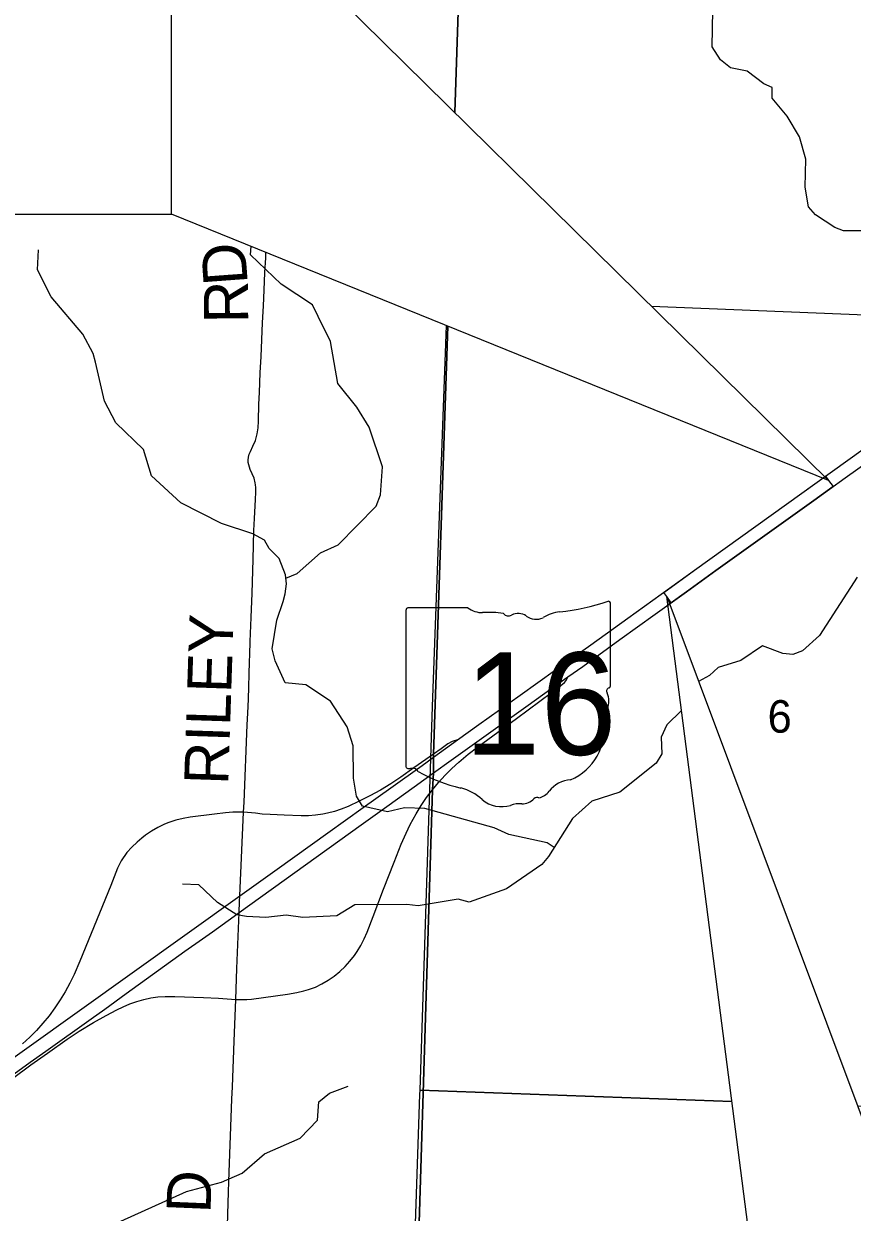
# Model space of a CAD drawing. Extents: x 0 to 34, y 0 to 22.
# Drawn here: x 25.673 to 26.74, y 15.788 to 17.319 of the extents above; entities that cross this region are included whole.
import ezdxf

# ---------------------------------------------------------------- set-up
doc = ezdxf.new("R2010")
doc.units = 0
for name, color, linetype in [('GM_X_Interchange_Ramps', 7, 'Continuous'), ('GM_X_Minor_River', 7, 'Continuous'), ('GM_X_Section', 7, 'Continuous'), ('GM_X_Section_Text', 7, 'Continuous'), ('GM_X_State_Location', 7, 'Continuous'), ('GM_X_State_Route', 7, 'Continuous'), ('GM_X_State_Shield', 7, 'Continuous'), ('GM_X_Township', 7, 'Continuous'), ('GM_X_Township_Road', 7, 'Continuous'), ('GM_X_Township_Road_Text', 7, 'Continuous'), ('SH_Data', 7, 'Continuous'), ('SH_Text', 7, 'Continuous')]:
    doc.layers.add(name, color=color, linetype=linetype)

msp = doc.modelspace()

# ---------------------------------------------------------------- linework, layer by layer
at = {"layer": 'GM_X_Interchange_Ramps'}
for points in [[(25.9458, 16.0619), (25.96, 16.0619), (25.9661, 16.0624), (26.0124, 16.0688), (26.0246, 16.0709), (26.0337, 16.073), (26.0397, 16.0748), (26.0485, 16.0781), (26.0569, 16.0821), (26.065, 16.0868), (26.0727, 16.0921), (26.0799, 16.098), (26.0867, 16.1044), (26.093, 16.1113), (26.0987, 16.1187), (26.1023, 16.1238), (26.1071, 16.1318), (26.1113, 16.1401), (26.1152, 16.1486), (26.123, 16.169), (26.1362, 16.204), (26.1497, 16.2388), (26.159, 16.262), (26.1653, 16.2762), (26.1707, 16.2874), (26.1782, 16.3011), (26.1847, 16.3117), (26.1917, 16.322), (26.1991, 16.332), (26.2071, 16.3416), (26.2154, 16.3508), (26.2242, 16.3596), (26.2334, 16.3679), (26.2454, 16.3779), (26.2577, 16.3874), (26.3073, 16.424), (26.3526, 16.4574), (26.3597, 16.4625), (26.3692, 16.4704), (26.3714, 16.473), (26.3738, 16.4775)], [(26.2315, 16.3964), (26.2246, 16.3943), (26.2191, 16.3913), (26.2103, 16.3849), (26.2007, 16.3781), (26.1753, 16.3603), (26.1584, 16.3484), (26.1454, 16.3398), (26.1321, 16.3318), (26.1185, 16.3243), (26.1046, 16.3173), (26.0905, 16.3108), (26.0818, 16.3073), (26.073, 16.3043), (26.064, 16.3019), (26.0579, 16.3007), (26.0487, 16.2994), (26.0394, 16.2988), (26.0301, 16.2987), (26.0084, 16.2996), (25.9903, 16.3003), (25.9798, 16.3009), (25.9714, 16.3019), (25.956, 16.3034)], [(25.956, 16.3034), (25.9467, 16.3035), (25.9422, 16.3034), (25.9327, 16.3026), (25.9183, 16.3009), (25.8873, 16.2967), (25.878, 16.2951), (25.8688, 16.293), (25.8598, 16.2902), (25.854, 16.2879), (25.8455, 16.2837), (25.8373, 16.279), (25.8296, 16.2736), (25.8248, 16.2697), (25.8189, 16.2647), (25.812, 16.2581), (25.8057, 16.2512), (25.7983, 16.2405), (25.7936, 16.2314), (25.7848, 16.2089), (25.745, 16.1112), (25.7375, 16.0941), (25.732, 16.083), (25.726, 16.0721), (25.7196, 16.0615), (25.7127, 16.0512), (25.7053, 16.0412), (25.6974, 16.0316), (25.6891, 16.0223), (25.6804, 16.0135), (25.6713, 16.0051)], [(25.6147, 15.9334), (25.6254, 15.9375), (25.6324, 15.9416), (25.6817, 15.978), (25.7032, 15.993), (25.7285, 16.0109), (25.7441, 16.0211), (25.7627, 16.0324), (25.7788, 16.0416), (25.7926, 16.0488), (25.801, 16.0528), (25.8096, 16.0565), (25.8183, 16.0596), (25.8273, 16.0621), (25.8364, 16.064), (25.8456, 16.0654), (25.8548, 16.066), (25.8673, 16.066), (25.9044, 16.0644), (25.9234, 16.0637), (25.9458, 16.0619)]]:
    msp.add_lwpolyline(points, dxfattribs=at)
at = {"layer": 'GM_X_Minor_River'}
for points in [[(26.753, 17.052), (26.7288, 17.0519), (26.7174, 17.0564), (26.6927, 17.0726), (26.6836, 17.0828), (26.6793, 17.1082), (26.6803, 17.1443), (26.6719, 17.1731), (26.6562, 17.1996), (26.6368, 17.2231), (26.6368, 17.2367), (26.6261, 17.2412), (26.6045, 17.2575), (26.5833, 17.2619), (26.5704, 17.2725), (26.5597, 17.2892), (26.5602, 17.3362)], [(26.3559, 16.2576), (26.3468, 16.2637), (26.2976, 16.2746), (26.2786, 16.2832), (26.1892, 16.308), (26.163, 16.309), (26.1415, 16.3036), (26.1093, 16.3111), (26.1013, 16.324), (26.0974, 16.3471), (26.0972, 16.3888), (26.0895, 16.4131), (26.0678, 16.4464), (26.0359, 16.4675), (26.0094, 16.4701), (25.9964, 16.4981), (25.9929, 16.5137), (25.9988, 16.5505), (26.0067, 16.5748), (26.0093, 16.5847), (26.0111, 16.5972), (26.0099, 16.609), (26.0019, 16.6302), (25.989, 16.643), (25.9829, 16.6536), (25.9677, 16.6619), (25.9275, 16.6751), (25.8751, 16.7018), (25.8371, 16.7366), (25.8272, 16.7703), (25.7914, 16.8047), (25.7769, 16.8328), (25.7653, 16.8828), (25.7623, 16.8942), (25.7489, 16.9188), (25.7082, 16.9672), (25.6906, 17.0017), (25.6917, 17.0275)], [(26.0104, 16.6048), (26.0251, 16.6109), (26.0552, 16.6372), (26.0779, 16.6475), (26.1265, 16.6974), (26.1321, 16.7122), (26.135, 16.7479), (26.1178, 16.799), (26.1017, 16.8251), (26.0774, 16.8554), (26.0677, 16.9096), (26.052, 16.9418), (26.0448, 16.9566), (26.0045, 16.9834), (25.965, 17.0212), (25.9656, 17.0322)], [(26.7462, 16.6058), (26.6977, 16.5309), (26.6759, 16.5111), (26.6634, 16.5065), (26.6505, 16.5076), (26.6243, 16.5177), (26.5964, 16.4987), (26.5673, 16.4898), (26.556, 16.4792), (26.542, 16.4717)], [(26.52, 16.4344), (26.501, 16.4156), (26.4939, 16.4), (26.4947, 16.3784), (26.4876, 16.3663), (26.4404, 16.3289), (26.4045, 16.3174), (26.3796, 16.2953), (26.3488, 16.2463), (26.3401, 16.236), (26.2948, 16.2047), (26.2465, 16.1875), (26.2324, 16.1913), (26.1806, 16.1827), (26.1662, 16.1846), (26.0992, 16.184), (26.0762, 16.1699), (26.0323, 16.1678), (26.0107, 16.1708), (25.9846, 16.1676), (25.9596, 16.1691), (25.9471, 16.1709), (25.9224, 16.1868), (25.8981, 16.2098), (25.8773, 16.2105)], [(25.5935, 15.6481), (25.603, 15.6439), (25.6487, 15.6623), (25.6589, 15.676), (25.6611, 15.6889), (25.6675, 15.6984), (25.7045, 15.7232), (25.7411, 15.7347), (25.7665, 15.745), (25.7977, 15.7766), (25.8824, 15.8148), (25.9274, 15.8268), (25.9542, 15.8382), (25.9829, 15.8634), (26.0286, 15.8836), (26.0512, 15.9065), (26.053, 15.9304), (26.0666, 15.9414), (26.0908, 15.9506)]]:
    msp.add_lwpolyline(points, dxfattribs=at)
at = {"layer": 'GM_X_Section'}
for points in [[(26.4812, 16.9552), (27.1069, 16.9297), (27.0827, 15.9122), (26.747, 15.9245)], [(26.585, 15.9305), (26.1833, 15.9453), (26.1992, 16.4394), (26.2171, 16.9301)], [(26.6512, 15.4179), (26.1658, 15.4276), (26.1831, 15.9395), (26.1833, 15.9453), (26.585, 15.9305)]]:
    msp.add_lwpolyline(points, dxfattribs=at)
at = {"layer": 'GM_X_State_Route'}
for points in [[(25.358, 15.7713), (25.3861, 15.7908), (25.4239, 15.8181), (25.487, 15.8634), (25.5552, 15.9122), (25.5625, 15.9174), (25.6056, 15.9485), (25.9511, 16.1955), (25.999, 16.2298), (26.0646, 16.2769), (26.1101, 16.3094), (26.1455, 16.3346), (26.1859, 16.3635), (26.2005, 16.374), (26.2315, 16.3964), (26.259, 16.4161), (26.3121, 16.454), (26.3576, 16.4865), (26.4031, 16.5189), (26.4511, 16.5533), (26.494, 16.5841), (26.5368, 16.615), (26.6554, 16.7), (26.7739, 16.7852)], [(25.6558, 15.9629), (25.6809, 15.9812), (25.701, 15.9957), (25.7594, 16.037), (25.7771, 16.0496), (25.8048, 16.0696), (25.8804, 16.1241), (25.9032, 16.1402), (25.9159, 16.1492), (25.9436, 16.1692), (25.9502, 16.1739), (26.1075, 16.2871), (26.1403, 16.3107), (26.1757, 16.3359), (26.2005, 16.3538), (26.2235, 16.3705), (26.3195, 16.439), (26.3549, 16.4642), (26.3738, 16.4775), (26.393, 16.4911), (26.4408, 16.5256), (26.4861, 16.5584), (26.5265, 16.5873), (26.5644, 16.6145), (26.6122, 16.649), (26.6906, 16.7049), (26.7309, 16.734), (26.7739, 16.7645)]]:
    msp.add_lwpolyline(points, dxfattribs=at)
at = {"layer": 'GM_X_State_Shield'}
for p, q in [((26.1651, 16.5632), (26.1651, 16.3631)), ((26.2449, 16.5666), (26.1677, 16.5666)), ((26.4287, 16.4669), (26.4287, 16.5716)), ((26.4287, 16.4669), (26.4287, 16.4669))]:
    msp.add_line(p, q, dxfattribs=at)
for centre, radius, start, end in [((26.1681, 16.5636), 0.00305, 98.1301, 188.1301), ((26.2633, 16.5899), 0.0296, 231.6195, 271.1119), ((26.3348, 16.8395), 0.2796, 275.8445, 288.9065), ((26.4258, 16.572), 0.00294, 351.8621, 97.738), ((26.2731, 16.4543), 0.1064, 80.4867, 94.9883), ((26.2972, 16.5646), 0.00855, 219.7921, 297.1024), ((26.3098, 16.5415), 0.0178, 54.4667, 119.1411), ((26.3327, 16.5732), 0.0214, 233.8562, 294.8282), ((26.3705, 16.5055), 0.0563, 97.3462, 120.7689), ((26.4281, 16.4592), 0.00454, 107.944, 210.337), ((26.3992, 16.446), 0.0273, 340.033, 23.6496), ((26.4256, 16.4665), 0.00314, 289.6038, 7.7341), ((26.4393, 16.4231), 0.0198, 136.8065, 186.9296), ((26.3505, 16.4098), 0.0699, 292.3089, 8.9858), ((26.1681, 16.3626), 0.00308, 171.9584, 258.3066), ((26.1686, 16.3831), 0.0235, 267.339, 280.6039), ((26.1734, 16.3515), 0.00848, 29.7484, 93.2717), ((26.2805, 16.5313), 0.2019, 240.4129, 257.1985), ((26.2203, 16.2732), 0.0632, 47.1842, 75.836), ((26.38, 16.3069), 0.0383, 94.4031, 142.5768), ((26.2886, 16.3505), 0.0401, 230.7004, 286.2918), ((26.3147, 16.3355), 0.0214, 268.777, 315.5493), ((26.334, 16.3162), 0.00601, 65.7517, 132.6484), ((26.3314, 16.3437), 0.0226, 282.8732, 323.2771), ((26.3118, 16.2813), 0.0329, 85.6951, 111.2099)]:
    msp.add_arc(centre, radius, start, end, dxfattribs=at)
at = {"layer": 'GM_X_Township'}
for points in [[(30.8167, 17.8174), (30.1304, 17.8301), (29.8296, 17.8449), (29.1279, 17.8574), (28.6324, 17.8677), (28.1264, 17.8728), (27.8903, 17.8826), (27.7531, 17.8783), (27.1422, 17.8906), (26.9072, 17.9017), (26.4988, 17.9198), (26.3979, 17.9244), (26.2521, 17.9299), (26.228, 17.2045)], [(26.228, 17.2045), (26.2521, 17.9299)], [(26.2189, 16.9294), (26.2007, 16.3781), (26.2005, 16.374), (26.2005, 16.3538), (26.1991, 16.332), (26.1747, 15.5373), (26.1374, 14.4382), (26.1244, 14.1)], [(26.1244, 14.1), (26.1374, 14.4382), (26.1747, 15.5373), (26.1991, 16.332), (26.2005, 16.3538), (26.2005, 16.374), (26.2007, 16.3781), (26.2189, 16.9294)]]:
    msp.add_lwpolyline(points, dxfattribs=at)
at = {"layer": 'GM_X_Township_Road'}
for points in [[(25.9639, 16.5064), (25.9642, 16.5231), (25.9655, 16.5541), (25.9668, 16.5852), (25.9683, 16.6286), (25.9693, 16.6659), (25.9699, 16.6814), (25.9713, 16.7061), (25.9717, 16.7154), (25.9716, 16.7216), (25.9714, 16.7247), (25.9709, 16.7277), (25.9694, 16.7336), (25.9645, 16.7448), (25.9634, 16.7477), (25.9626, 16.7506), (25.962, 16.7536), (25.9617, 16.7566), (25.9621, 16.7607), (25.9631, 16.7643), (25.9649, 16.7679), (25.968, 16.7746), (25.9714, 16.7822), (25.9736, 16.7906), (25.9746, 16.7982), (25.9752, 16.8067), (25.9756, 16.8289), (25.9765, 16.844), (25.9774, 16.8692), (25.9787, 16.8902), (25.9805, 16.9336), (25.9815, 16.9553), (25.9823, 16.9755), (25.9834, 16.9986), (25.9845, 17.0171), (25.9845, 17.0245)], [(25.956, 16.3034), (25.9567, 16.3162), (25.9607, 16.4157), (25.9614, 16.431), (25.9622, 16.449), (25.9637, 16.497), (25.9639, 16.5064)], [(25.9458, 16.0619), (25.9474, 16.1019), (25.9502, 16.1739), (25.9507, 16.1884), (25.9511, 16.1955), (25.956, 16.3034)], [(25.9371, 15.8278), (25.9409, 15.9335), (25.9417, 15.9495), (25.9436, 16.0083), (25.9458, 16.0619)], [(25.9322, 15.6978), (25.9346, 15.7567), (25.9366, 15.814), (25.9371, 15.8278)]]:
    msp.add_lwpolyline(points, dxfattribs=at)
at = {"layer": 'SH_Data'}
for p, q in [((26.7055, 16.736), (26.7096, 16.7303)), ((26.7096, 16.7303), (26.7152, 16.7226)), ((26.5011, 16.5809), (26.4971, 16.5864)), ((26.5066, 16.5731), (26.5011, 16.5809))]:
    msp.add_line(p, q, dxfattribs=at)
for points in [[(26.4971, 16.5864), (26.5368, 16.615), (26.6554, 16.7), (26.7055, 16.736)], [(26.7152, 16.7226), (26.6906, 16.7049), (26.6122, 16.649), (26.5644, 16.6145), (26.5265, 16.5873), (26.5066, 16.5731)]]:
    msp.add_lwpolyline(points, dxfattribs=at)
at = {"layer": 'SH_Text'}
for points in [[(24.3906, 17.0737), (25.8632, 17.0737), (25.8632, 17.5637), (24.3906, 17.5637)], [(26.7096, 16.7303), (25.8632, 17.0737), (25.8632, 17.5637)], [(26.5011, 16.5809), (27.1585, 14.8261), (26.7275, 14.8261)]]:
    msp.add_lwpolyline(points, close=True, dxfattribs=at)

# ---------------------------------------------------------------- texts
at = {"layer": 'GM_X_Section_Text'}
msp.add_text('6', height=0.0419, rotation=0, dxfattribs=at).set_placement((26.6309, 16.4057))
at = {"layer": 'GM_X_State_Location'}
for s in ['s', 'r']:
    msp.add_text(s, height=0.000189, dxfattribs=at).set_placement((26.4936, 16.5405))
msp.add_text('16', height=0.000189, rotation=0, dxfattribs=at).set_placement((26.4459, 16.5268))
at = {"layer": 'GM_X_State_Shield'}
msp.add_text('16', height=0.13184, dxfattribs=at).set_placement((26.2403, 16.3772))
at = {"layer": 'GM_X_Township_Road_Text'}
for s, height, rotation, p in [('D', 0.0568, 94.2008, (25.9614, 16.9839)), ('R', 0.0568, 90.4059, (25.9619, 16.9332)), ('RILEY', 0.05682, 88.1441, (25.9361, 16.338)), ('D', 0.0568, 87.6753, (25.9131, 15.7861))]:
    msp.add_text(s, height=height, rotation=rotation, dxfattribs=at).set_placement(p)

doc.saveas('drawing.dxf')
